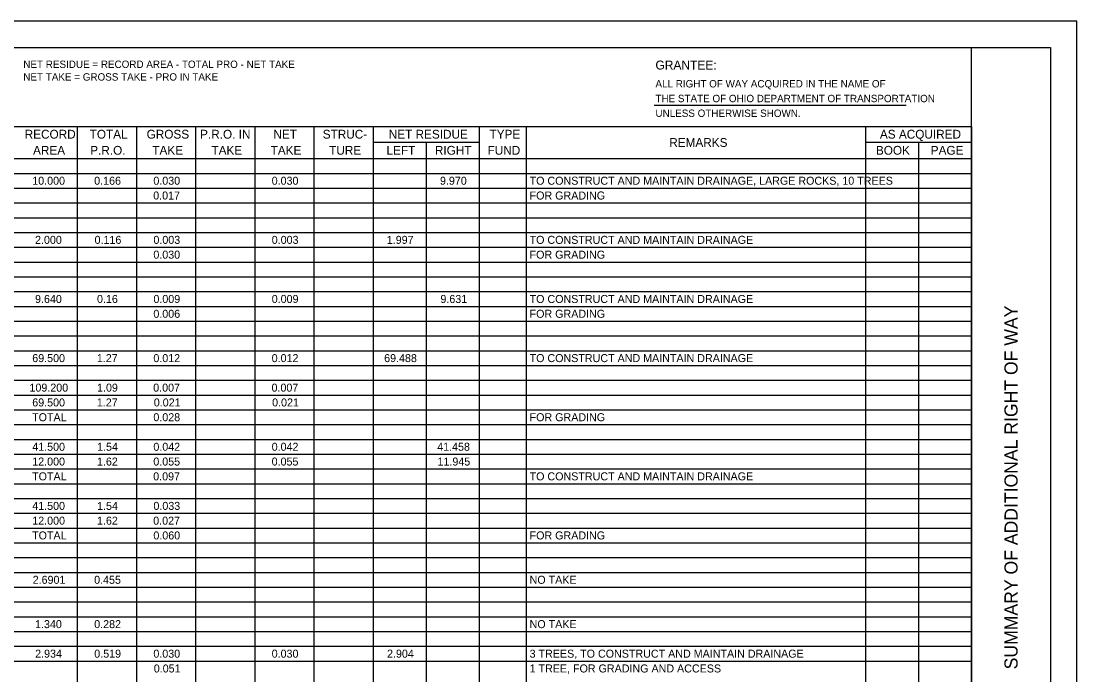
# Model space of a CAD drawing. Extents: x 0 to 34, y 0 to 22.
# Drawn here: x 13.96 to 34, y 9.58 to 22 of the extents above; entities that cross this region are included whole.
import ezdxf

# ---------------------------------------------------------------- set-up
doc = ezdxf.new("R2010")
doc.units = 0
for name, color, linetype in [('SH_Border', 7, 'Continuous'), ('SH_Cut_Line', 7, 'Continuous'), ('SH_Data', 7, 'Continuous'), ('SH_Text', 7, 'Continuous')]:
    doc.layers.add(name, color=color, linetype=linetype)

msp = doc.modelspace()

# ---------------------------------------------------------------- linework, layer by layer
at = {"layer": 'SH_Border'}
msp.add_line((32, 0.5), (32, 21.5), dxfattribs=at)
msp.add_lwpolyline([(1.5, 21.5), (33.5, 21.5), (33.5, 0.5), (1.5, 0.5)], close=True, dxfattribs=at)
at = {"layer": 'SH_Cut_Line'}
msp.add_lwpolyline([(0, 0), (34, 0), (34, 22), (0, 22)], close=True, dxfattribs=at)
at = {"layer": 'SH_Text'}
for p, q in [((25.978, 20.403), (30.759, 20.403)), ((1.5, 20), (32, 20)), ((1.5, 20), (32, 20)), ((15.024, 20), (15.024, 19.389)), ((16.147, 20), (16.147, 19.389)), ((17.27, 20), (17.27, 19.389)), ((18.393, 20), (18.393, 19.389)), ((19.516, 20), (19.516, 19.389)), ((20.639, 20), (20.639, 19.389)), ((22.653, 20), (22.653, 19.389)), ((23.545, 20), (23.545, 19.389)), ((29.985, 20), (29.985, 19.389)), ((32, 20), (32, 19.389)), ((20.639, 19.703), (22.653, 19.703)), ((21.646, 19.703), (21.646, 19.389)), ((29.985, 19.703), (32, 19.703)), ((30.993, 19.703), (30.993, 19.389)), ((1.5, 19.389), (32, 19.389)), ((1.5, 19.389), (32, 19.389)), ((15.024, 19.389), (15.024, 5.353)), ((16.147, 19.389), (16.147, 5.353)), ((17.27, 19.389), (17.27, 5.353)), ((18.393, 19.389), (18.393, 5.353)), ((19.516, 19.389), (19.516, 5.353)), ((20.639, 19.389), (20.639, 5.353)), ((21.646, 19.389), (21.646, 5.353)), ((22.653, 19.389), (22.653, 5.353)), ((23.545, 19.389), (23.545, 5.353)), ((29.985, 19.389), (29.985, 5.353)), ((30.993, 19.389), (30.993, 5.353)), ((32, 19.389), (32, 5.353)), ((1.5, 19.108), (32, 19.108)), ((1.5, 18.828), (32, 18.828)), ((1.5, 18.547), (32, 18.547)), ((1.5, 18.266), (32, 18.266)), ((1.5, 17.985), (32, 17.985)), ((1.5, 17.705), (32, 17.705)), ((1.5, 17.424), (32, 17.424)), ((1.5, 17.143), (32, 17.143)), ((1.5, 16.862), (32, 16.862)), ((1.5, 16.582), (32, 16.582)), ((1.5, 16.301), (32, 16.301)), ((1.5, 16.02), (32, 16.02)), ((1.5, 15.74), (32, 15.74)), ((1.5, 15.459), (32, 15.459)), ((1.5, 15.178), (32, 15.178)), ((1.5, 14.897), (32, 14.897)), ((1.5, 14.617), (32, 14.617)), ((1.5, 14.336), (32, 14.336)), ((1.5, 14.055), (32, 14.055)), ((1.5, 13.774), (32, 13.774)), ((1.5, 13.494), (32, 13.494)), ((1.5, 13.213), (32, 13.213)), ((1.5, 12.932), (32, 12.932)), ((1.5, 12.652), (32, 12.652)), ((1.5, 12.371), (32, 12.371)), ((1.5, 12.09), (32, 12.09)), ((1.5, 11.809), (32, 11.809)), ((1.5, 11.529), (32, 11.529)), ((1.5, 11.248), (32, 11.248)), ((1.5, 10.967), (32, 10.967)), ((1.5, 10.687), (32, 10.687)), ((1.5, 10.406), (32, 10.406)), ((1.5, 10.125), (32, 10.125)), ((1.5, 9.844), (32, 9.844))]:
    msp.add_line(p, q, dxfattribs=at)

# ---------------------------------------------------------------- texts
at = {"layer": 'SH_Data'}
msp.add_text('SUMMARY OF ADDITIONAL RIGHT OF WAY', height=0.25, rotation=90, dxfattribs=at).set_placement((32.875, 9.687))
at = {"layer": 'SH_Text'}
for s, height, p in [('NET RESIDUE = RECORD AREA - TOTAL PRO - NET TAKE', 0.14, (14, 21.11)), ('GRANTEE:', 0.17, (26, 21.08)), ('NET TAKE = GROSS TAKE - PRO IN TAKE', 0.14, (14, 20.87)), ('ALL RIGHT OF WAY ACQUIRED IN THE NAME OF', 0.14, (26, 20.74)), ('THE STATE OF OHIO DEPARTMENT OF TRANSPORTATION', 0.14, (26, 20.46)), ('UNLESS OTHERWISE SHOWN.', 0.14, (26, 20.18)), ('RECORD', 0.1671, (14.026, 19.768)), ('TOTAL', 0.1671, (15.26, 19.768)), ('GROSS', 0.1671, (16.341, 19.768)), ('P.R.O. IN', 0.1671, (17.356, 19.768)), ('NET', 0.1671, (18.748, 19.768)), ('STRUC-', 0.1671, (19.684, 19.768)), ('NET RESIDUE', 0.16711, (20.937, 19.768)), ('TYPE', 0.1671, (22.85, 19.768)), ('AS ACQUIRED', 0.16711, (30.261, 19.768)), ('REMARKS', 0.1671, (26.262, 19.611)), ('AREA', 0.1671, (14.185, 19.462)), ('P.R.O.', 0.1671, (15.27, 19.462)), ('TAKE', 0.1671, (16.449, 19.462)), ('TAKE', 0.1671, (17.572, 19.462)), ('TAKE', 0.1671, (18.695, 19.462)), ('TURE', 0.1671, (19.806, 19.462)), ('LEFT', 0.1671, (20.895, 19.462)), ('RIGHT', 0.1671, (21.813, 19.462)), ('FUND', 0.1671, (22.813, 19.462)), ('BOOK', 0.1671, (30.185, 19.462)), ('PAGE', 0.1671, (31.226, 19.462)), ('10.000', 0.1519, (14.17, 18.892)), ('0.166', 0.1519, (15.346, 18.892)), ('0.030', 0.1519, (16.469, 18.892)), ('0.030', 0.1519, (18.715, 18.892)), ('9.970', 0.1519, (21.91, 18.892)), ('TO CONSTRUCT AND MAINTAIN DRAINAGE, LARGE ROCKS, 10 TREES', 0.15192, (23.611, 18.892)), ('0.017', 0.1519, (16.466, 18.611)), ('FOR GRADING', 0.15192, (23.611, 18.611)), ('2.000', 0.1519, (14.223, 17.769)), ('0.116', 0.1519, (15.353, 17.769)), ('0.003', 0.1519, (16.47, 17.769)), ('0.003', 0.1519, (18.716, 17.769)), ('1.997', 0.1519, (20.9, 17.769)), ('TO CONSTRUCT AND MAINTAIN DRAINAGE', 0.15192, (23.611, 17.769)), ('0.030', 0.1519, (16.469, 17.488)), ('FOR GRADING', 0.15192, (23.611, 17.488)), ('9.640', 0.1519, (14.223, 16.646)), ('0.16', 0.1519, (15.399, 16.646)), ('0.009', 0.1519, (16.47, 16.646)), ('0.009', 0.1519, (18.716, 16.646)), ('9.631', 0.1519, (21.918, 16.646)), ('TO CONSTRUCT AND MAINTAIN DRAINAGE', 0.15192, (23.611, 16.646)), ('0.006', 0.1519, (16.469, 16.365)), ('FOR GRADING', 0.15192, (23.611, 16.365)), ('69.500', 0.1519, (14.17, 15.523)), ('1.27', 0.1519, (15.396, 15.523)), ('0.012', 0.1519, (16.469, 15.523)), ('0.012', 0.1519, (18.715, 15.523)), ('69.488', 0.1519, (20.85, 15.523)), ('TO CONSTRUCT AND MAINTAIN DRAINAGE', 0.15192, (23.611, 15.523)), ('109.200', 0.1519, (14.117, 14.962)), ('1.09', 0.1519, (15.4, 14.962)), ('0.007', 0.1519, (16.466, 14.962)), ('0.007', 0.1519, (18.712, 14.962)), ('69.500', 0.1519, (14.17, 14.681)), ('1.27', 0.1519, (15.396, 14.681)), ('0.021', 0.1519, (16.477, 14.681)), ('0.021', 0.1519, (18.723, 14.681)), ('TOTAL', 0.1519, (14.167, 14.4)), ('0.028', 0.1519, (16.469, 14.4)), ('FOR GRADING', 0.15192, (23.611, 14.4)), ('41.500', 0.1519, (14.17, 13.839)), ('1.54', 0.1519, (15.401, 13.839)), ('0.042', 0.1519, (16.469, 13.839)), ('0.042', 0.1519, (18.715, 13.839)), ('41.458', 0.1519, (21.857, 13.839)), ('12.000', 0.1519, (14.17, 13.558)), ('1.62', 0.1519, (15.399, 13.558)), ('0.055', 0.1519, (16.468, 13.558)), ('0.055', 0.1519, (18.714, 13.558)), ('11.945', 0.1519, (21.863, 13.558)), ('TOTAL', 0.1519, (14.167, 13.277)), ('0.097', 0.1519, (16.466, 13.277)), ('TO CONSTRUCT AND MAINTAIN DRAINAGE', 0.15192, (23.611, 13.277)), ('41.500', 0.1519, (14.17, 12.716)), ('1.54', 0.1519, (15.401, 12.716)), ('0.033', 0.1519, (16.47, 12.716)), ('12.000', 0.1519, (14.17, 12.435)), ('1.62', 0.1519, (15.399, 12.435)), ('0.027', 0.1519, (16.466, 12.435)), ('TOTAL', 0.1519, (14.167, 12.155)), ('0.060', 0.1519, (16.469, 12.155)), ('FOR GRADING', 0.15192, (23.611, 12.155)), ('2.6901', 0.1519, (14.178, 11.312)), ('0.455', 0.1519, (15.345, 11.312)), ('NO TAKE', 0.1519, (23.611, 11.312)), ('1.340', 0.1519, (14.223, 10.47)), ('0.282', 0.1519, (15.346, 10.47)), ('NO TAKE', 0.1519, (23.611, 10.47)), ('2.934', 0.1519, (14.225, 9.909)), ('0.519', 0.1519, (15.347, 9.909)), ('0.030', 0.1519, (16.469, 9.909)), ('0.030', 0.1519, (18.715, 9.909)), ('2.904', 0.1519, (20.905, 9.909)), ('3 TREES, TO CONSTRUCT AND MAINTAIN DRAINAGE', 0.15192, (23.611, 9.909)), ('0.051', 0.1519, (16.477, 9.628)), ('1 TREE, FOR GRADING AND ACCESS', 0.15192, (23.611, 9.628))]:
    msp.add_text(s, height=height, dxfattribs=at).set_placement(p)

doc.saveas('drawing.dxf')
